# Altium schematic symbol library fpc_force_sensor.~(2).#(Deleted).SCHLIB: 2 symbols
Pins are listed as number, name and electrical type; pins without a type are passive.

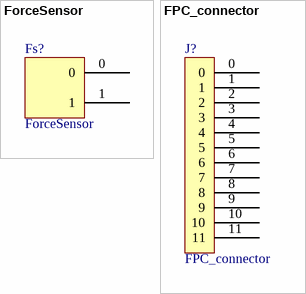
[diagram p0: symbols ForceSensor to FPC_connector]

## ForceSensor
designator Fs?
footprint sensor_connector
pins: 0, 1

## FPC_connector
designator J?
footprint FPC_connector
pins: 0, 1, 2, 3, 4, 5, 6, 7, 8, 9, 10, 11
